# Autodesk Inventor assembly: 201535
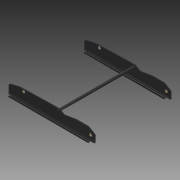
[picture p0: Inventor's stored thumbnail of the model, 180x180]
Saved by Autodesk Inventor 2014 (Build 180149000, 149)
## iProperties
Created: 2007-12
Part Number: 201535
Document SubType Name: Assembly
Designer: MM
Mass: 2432.15 g
Surface Area: 2875.32 cm^2
Volume: 309.75 cm^3
Density: 7.85198 g/cm^3
Description: BOTTOM GUIDE RAIL ASSEMBLY
Component Category: Lower Component
Author: MM
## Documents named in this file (7)
- C:\Users\iTools\Desktop\tutorial files\Automotive\2000\201535.iam
- C:\Users\iTools\Desktop\tutorial files\Automotive\2000\200468.ipt
- C:\Users\iTools\Desktop\tutorial files\Automotive\2000\200875.ipt
- C:\Users\iTools\Desktop\tutorial files\Automotive\2000\200050.ipt
- C:\Users\iTools\Desktop\tutorial files\Automotive\2000\200547.ipt
- C:\Users\iTools\Desktop\tutorial files\Automotive\2000\200682.ipt
- C:\Users\iTools\Desktop\tutorial files\Automotive\8000\800036.ipt
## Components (9 placed, 6 different names)
1. 200468:1 — Mate:1, Mate:2, Mate:3, Flush:2, Flush:3, Flush:7, Flush:8, Insert:1, Insert:2, Insert:3
2. 200875:1 — Mate:3, Flush:2, Flush:3
3. 200050:1 — Flush:6, Flush:7, Flush:8, Mate:4, Flush:9, Flush:10
4. 200547:1 — Mate:4, Flush:9, Flush:10, Insert:4, Insert:5
5. 200682:1 — Insert:1
6. 800036:1 — Insert:3
7. 800036:2 — Insert:2
8. 800036:3 — Insert:5
9. 800036:4 — Insert:4
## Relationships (16: Flush 7, Insert 5, Mate 4)
- Mate:1: 200468:1
- Mate:2: 200468:1
- Mate:3: 200468:1 ↔ 200875:1
- Flush:2: 200468:1 ↔ 200875:1
- Flush:3: 200468:1 ↔ 200875:1
- Flush:6: 200050:1
- Flush:7: 200468:1 ↔ 200050:1
- Flush:8: 200468:1 ↔ 200050:1
- Mate:4: 200050:1 ↔ 200547:1
- Flush:9: 200050:1 ↔ 200547:1
- Flush:10: 200050:1 ↔ 200547:1
- Insert:1: 200468:1 ↔ 200682:1
- Insert:2: 200468:1 ↔ 800036:2
- Insert:3: 200468:1 ↔ 800036:1
- Insert:4: 200547:1 ↔ 800036:4
- Insert:5: 200547:1 ↔ 800036:3
